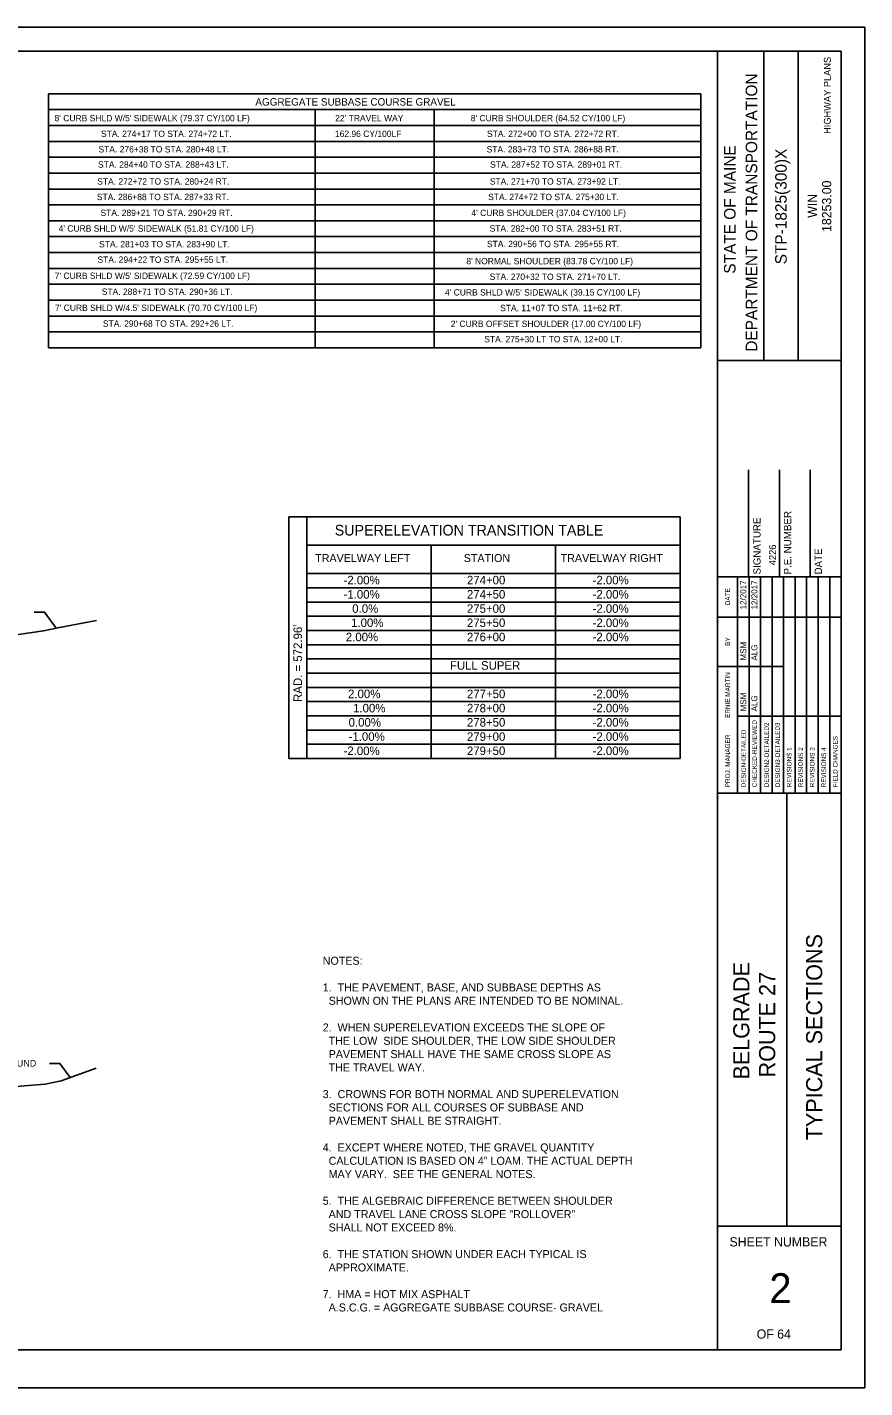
# Model space of a CAD drawing. Extents: x -60 to 130, y -2 to 86.
# Drawn here: x 75.3 to 129.5, y -2.4 to 85.6 of the extents above; entities that cross this region are included whole.
import ezdxf

# ---------------------------------------------------------------- set-up
doc = ezdxf.new("R2010")
doc.units = 0
for name, color, linetype in [('ANNOTATION', 7, 'Continuous'), ('BORDER', 7, 'Continuous'), ('PLOT BOUNDARY', 7, 'Continuous'), ('S_Roadway_Centerline', 7, 'Continuous')]:
    doc.layers.add(name, color=color, linetype=linetype)

msp = doc.modelspace()

# ---------------------------------------------------------------- linework, layer by layer
at = {"layer": 'ANNOTATION'}
for p, q in [((76.713, 81.246), (118.912, 81.246)), ((76.713, 81.246), (76.713, 64.821)), ((118.912, 81.246), (118.912, 64.821)), ((93.963, 80.22), (93.963, 64.821)), ((101.662, 80.22), (101.662, 64.821)), ((76.713, 79.193), (118.912, 79.193)), ((76.713, 78.166), (118.912, 78.166)), ((76.713, 76.113), (118.912, 76.113)), ((76.713, 76.113), (118.912, 76.113)), ((76.713, 75.087), (118.912, 75.087)), ((76.713, 73.034), (118.912, 73.034)), ((76.713, 72.007), (118.912, 72.007)), ((76.713, 70.98), (118.912, 70.98)), ((76.713, 68.927), (118.912, 68.927)), ((76.713, 66.874), (118.912, 66.874)), ((76.713, 65.847), (118.912, 65.847)), ((76.713, 64.821), (118.912, 64.821)), ((92.272, 53.891), (117.572, 53.891)), ((92.272, 53.891), (92.272, 38.251)), ((93.422, 53.891), (93.422, 38.251)), ((117.572, 53.891), (117.572, 38.251)), ((93.422, 52.051), (117.572, 52.051)), ((101.472, 52.051), (101.472, 38.251)), ((109.522, 52.051), (109.522, 38.251)), ((93.422, 50.211), (117.572, 50.211)), ((93.422, 50.211), (101.472, 50.211)), ((93.422, 49.291), (117.572, 49.291)), ((93.422, 48.371), (117.572, 48.371)), ((93.422, 47.451), (117.572, 47.451)), ((93.422, 46.531), (117.572, 46.531)), ((93.422, 45.611), (117.572, 45.611)), ((93.422, 44.691), (117.572, 44.691)), ((93.422, 43.771), (117.572, 43.771)), ((93.422, 42.851), (117.572, 42.851)), ((93.422, 41.931), (117.572, 41.931)), ((93.422, 41.011), (117.572, 41.011)), ((93.422, 40.091), (117.572, 40.091)), ((93.422, 39.171), (117.572, 39.171)), ((92.272, 38.251), (117.572, 38.251))]:
    msp.add_line(p, q, dxfattribs=at)
for points in [[(76.713, 80.22), (87.119, 80.22), (95.674, 80.22), (104.229, 80.22), (118.912, 80.22)], [(76.713, 77.14), (87.119, 77.14), (95.674, 77.14), (104.229, 77.14), (118.912, 77.14)], [(76.713, 74.06), (87.119, 74.06), (95.674, 74.06), (104.229, 74.06), (118.912, 74.06)], [(76.713, 69.954), (87.119, 69.954), (95.674, 69.954), (104.229, 69.954), (118.912, 69.954)], [(76.713, 67.901), (87.119, 67.901), (95.674, 67.901), (104.229, 67.901), (118.912, 67.901)], [(75.78, 47.721), (76.46, 47.721), (77.219, 46.681)], [(76.78, 18.537), (77.46, 18.537), (78.127, 17.622)]]:
    msp.add_lwpolyline(points, dxfattribs=at)
at = {"layer": 'BORDER'}
for p, q in [((128, 84), (0, 84)), ((120, 0.002), (120, 84.002)), ((122.983, 63.997), (122.983, 83.997)), ((125.219, 63.997), (125.219, 83.997)), ((128, 0.002), (128, 84.002)), ((120, 63.995), (128, 63.995)), ((122, 50.002), (122, 56.92)), ((124, 50.002), (124, 56.92)), ((126, 50.002), (126, 56.92)), ((120, 50.002), (128, 50.002)), ((120, 36.002), (128, 36.002)), ((124.473, 8.002), (124.473, 36.002)), ((120, 8.002), (128, 8.002)), ((0, 0), (128, 0))]:
    msp.add_line(p, q, dxfattribs=at)
for points in [[(121.292, 47.402), (121.292, 50.002)], [(121.292, 36.005), (121.292, 49.437)], [(122.038, 36.005), (122.038, 50.002)], [(122.783, 50.002), (122.783, 36.005)], [(123.528, 36.005), (123.528, 50.002)], [(124.274, 36.005), (124.274, 50.002)], [(125.019, 36.005), (125.019, 50.002)], [(125.764, 36.005), (125.764, 50.002)], [(126.51, 36.005), (126.51, 50.002)], [(127.255, 36.005), (127.255, 50.002)], [(120, 47.402), (128, 47.402)], [(120, 44.202), (121.292, 44.202)], [(121.292, 44.202), (124.273, 44.202)], [(121.292, 41.002), (128, 41.002)]]:
    msp.add_lwpolyline(points, dxfattribs=at)
at = {"layer": 'PLOT BOUNDARY'}
msp.add_lwpolyline([(-6.475, -2.447), (129.525, -2.447), (129.525, 85.553), (-6.475, 85.553)], close=True, dxfattribs=at)
at = {"layer": 'S_Roadway_Centerline'}
for points in [[(73.593, 46.137), (74.772, 46.277), (76.387, 46.507), (77.428, 46.724), (79.821, 47.173)], [(72.871, 16.659), (74.887, 17.051), (76.503, 17.192), (77.544, 17.409), (79.799, 18.233)]]:
    msp.add_lwpolyline(points, dxfattribs=at)

# ---------------------------------------------------------------- texts
at = {"layer": 'ANNOTATION'}
for s, height, p in [(' AGGREGATE SUBBASE COURSE GRAVEL', 0.47908, (89.923, 80.484)), ("8' CURB SHLD W/5' SIDEWALK (79.37 CY/100 LF)", 0.41064, (77.109, 79.468)), ("22' TRAVEL WAY", 0.41064, (95.267, 79.468)), ("8' CURB SHOULDER (64.52 CY/100 LF)", 0.41064, (104.035, 79.468)), ('STA. 274+17 TO STA. 274+72 LT.', 0.41064, (80.113, 78.455)), ('162.96 CY/100LF', 0.41064, (95.245, 78.455)), ('STA. 272+00 TO STA. 272+72 RT.', 0.41064, (105.086, 78.455)), ('STA. 276+38 TO STA. 280+48 LT.', 0.41064, (79.949, 77.452)), ('STA. 283+73 TO STA. 286+88 RT.', 0.41064, (105.06, 77.452)), ('STA. 284+40 TO STA. 288+43 LT.', 0.41064, (79.92, 76.467)), ('STA. 287+52 TO STA. 289+01 RT.', 0.41064, (105.284, 76.467)), ('STA. 272+72 TO STA. 280+24 RT.', 0.41064, (79.868, 75.373)), ('STA. 271+70 TO STA. 273+92 LT.', 0.41064, (105.265, 75.373)), ('STA. 286+88 TO STA. 287+33 RT.', 0.41064, (79.846, 74.369)), ('STA. 274+72 TO STA. 275+30 LT.', 0.41064, (105.155, 74.369)), ('STA. 289+21 TO STA. 290+29 RT.', 0.41064, (80.081, 73.343)), ("4' CURB SHOULDER (37.04 CY/100 LF)", 0.41064, (104.079, 73.343)), ("4' CURB SHLD W/5' SIDEWALK (51.81 CY/100 LF)", 0.41064, (77.373, 72.33)), ('STA. 282+00 TO STA. 283+51 RT.', 0.41064, (105.254, 72.331)), ('STA. 281+03 TO STA. 283+90 LT.', 0.41064, (79.989, 71.318)), ('STA. 290+56 TO STA. 295+55 RT.', 0.41064, (105.082, 71.327)), ('STA. 294+22 TO STA. 295+55 LT.', 0.41064, (79.883, 70.314)), ("8' NORMAL SHOULDER (83.78 CY/100 LF)", 0.41064, (103.747, 70.22)), ("7' CURB SHLD W/5' SIDEWALK (72.59 CY/100 LF)", 0.41064, (77.119, 69.273)), ('STA. 270+32 TO STA. 271+70 LT.', 0.41064, (105.258, 69.208)), ('STA. 288+71 TO STA. 290+36 LT.', 0.41064, (80.161, 68.24)), ("4' CURB SHLD W/5' SIDEWALK (39.15 CY/100 LF)", 0.41064, (102.364, 68.198)), ("7' CURB SHLD W/4.5' SIDEWALK (70.70 CY/100 LF)", 0.41064, (77.136, 67.201)), ('STA. 11+07 TO STA. 11+62 RT.', 0.41064, (105.932, 67.186)), ('STA. 290+68 TO STA. 292+26 LT.', 0.41064, (80.236, 66.177)), ("2' CURB OFFSET SHOULDER (17.00 CY/100 LF)", 0.41064, (102.742, 66.165)), ('STA. 275+30 LT TO STA. 12+00 LT.', 0.41064, (104.907, 65.172)), ('SUPERELEVATION TRANSITION TABLE', 0.69, (95.232, 52.676)), ('TRAVELWAY LEFT', 0.5175, (93.97, 50.961)), ('STATION', 0.5175, (103.58, 50.961)), ('TRAVELWAY RIGHT', 0.5175, (109.85, 50.961)), ('-2.00%', 0.552, (95.804, 49.516)), ('274+00', 0.552, (103.786, 49.516)), ('-2.00%', 0.552, (111.915, 49.516)), ('-1.00%', 0.552, (95.804, 48.596)), ('274+50', 0.552, (103.786, 48.596)), ('-2.00%', 0.552, (111.915, 48.596)), ('0.0%', 0.552, (96.367, 47.676)), ('275+00', 0.552, (103.786, 47.676)), ('-2.00%', 0.552, (111.915, 47.676)), ('1.00%', 0.552, (96.293, 46.756)), ('275+50', 0.552, (103.786, 46.756)), ('-2.00%', 0.552, (111.915, 46.756)), ('2.00%', 0.552, (95.952, 45.836)), ('276+00', 0.552, (103.786, 45.836)), ('-2.00%', 0.552, (111.915, 45.836)), ('FULL SUPER', 0.552, (102.687, 43.996)), ('2.00%', 0.552, (96.096, 42.156)), ('277+50', 0.552, (103.786, 42.156)), ('-2.00%', 0.552, (111.915, 42.156)), ('1.00%', 0.552, (96.422, 41.236)), ('278+00', 0.552, (103.786, 41.236)), ('-2.00%', 0.552, (111.915, 41.236)), ('0.00%', 0.552, (96.132, 40.316)), ('278+50', 0.552, (103.786, 40.316)), ('-2.00%', 0.552, (111.915, 40.316)), ('-1.00%', 0.552, (96.132, 39.396)), ('279+00', 0.552, (103.786, 39.396)), ('-2.00%', 0.552, (111.915, 39.396)), ('-2.00%', 0.552, (95.804, 38.476)), ('279+50', 0.552, (103.786, 38.476)), ('-2.00%', 0.552, (111.915, 38.476)), ('NOTES:', 0.5175, (94.456, 24.914)), ('1.  THE PAVEMENT, BASE, AND SUBBASE DEPTHS AS', 0.5175, (94.456, 23.189)), ('  SHOWN ON THE PLANS ARE INTENDED TO BE NOMINAL.', 0.5175, (94.456, 22.326)), ('2.  WHEN SUPERELEVATION EXCEEDS THE SLOPE OF', 0.5175, (94.456, 20.601)), ('  THE LOW  SIDE SHOULDER, THE LOW SIDE SHOULDER', 0.5175, (94.456, 19.739)), ('  PAVEMENT SHALL HAVE THE SAME CROSS SLOPE AS', 0.5175, (94.456, 18.876)), ('EXISTING GROUND', 0.4335, (70.482, 18.325)), ('  THE TRAVEL WAY.', 0.5175, (94.456, 18.014)), ('3.  CROWNS FOR BOTH NORMAL AND SUPERELEVATION', 0.5175, (94.456, 16.289)), ('  SECTIONS FOR ALL COURSES OF SUBBASE AND', 0.5175, (94.456, 15.426)), ('  PAVEMENT SHALL BE STRAIGHT.', 0.5175, (94.456, 14.564)), ('4.  EXCEPT WHERE NOTED, THE GRAVEL QUANTITY', 0.5175, (94.456, 12.839)), ('  CALCULATION IS BASED ON 4" LOAM. THE ACTUAL DEPTH', 0.5175, (94.456, 11.976)), ('  MAY VARY.  SEE THE GENERAL NOTES.', 0.5175, (94.456, 11.114)), ('5.  THE ALGEBRAIC DIFFERENCE BETWEEN SHOULDER', 0.5175, (94.456, 9.389)), ('  AND TRAVEL LANE CROSS SLOPE "ROLLOVER"', 0.5175, (94.456, 8.526)), ('  SHALL NOT EXCEED 8%.', 0.5175, (94.456, 7.664)), ('6.  THE STATION SHOWN UNDER EACH TYPICAL IS', 0.5175, (94.456, 5.939)), ('  APPROXIMATE.', 0.5175, (94.456, 5.076)), ('7.  HMA = HOT MIX ASPHALT', 0.5175, (94.456, 3.351)), ('  A.S.C.G. = AGGREGATE SUBBASE COURSE- GRAVEL', 0.5175, (94.456, 2.489))]:
    msp.add_text(s, height=height, dxfattribs=at).set_placement(p)
for s, height, p in [('4226', 0.45, (123.782, 50.753)), ("RAD. = 572.96'", 0.552, (93.118, 41.913))]:
    msp.add_text(s, height=height, rotation=90, dxfattribs=at).set_placement(p)
at = {"layer": 'BORDER'}
for s, height, p in [('HIGHWAY PLANS', 0.44721, (127.326, 78.652)), ('DEPARTMENT OF TRANSPORTATION', 0.7454, (122.565, 64.565)), ('STATE OF MAINE', 0.7454, (121.164, 69.609)), ('STP-1825(300)X', 0.7454, (124.473, 70.217)), ('18253.00', 0.5962, (127.356, 72.309)), ('WIN', 0.5962, (126.429, 73.224)), ('SIGNATURE', 0.4724, (122.784, 50.156)), ('P.E. NUMBER', 0.47244, (124.768, 50.156)), ('DATE', 0.4724, (126.753, 50.156)), ('12/2017', 0.3876, (121.858, 47.896)), ('12/2017', 0.3876, (122.574, 47.896)), ('DATE', 0.2971, (120.803, 48.167)), ('BY', 0.2971, (120.803, 45.55)), ('MSM', 0.3876, (121.858, 44.59)), ('ALG', 0.3876, (122.574, 44.59)), ('ERNIE MARTIN', 0.2982, (120.803, 40.878)), ('MSM', 0.3876, (121.858, 41.301)), ('ALG', 0.3876, (122.574, 41.301)), ('CHECKED-REVIEWED', 0.2982, (122.545, 36.393)), ('PROJ. MANAGER', 0.2982, (120.803, 36.393)), ('DESIGN-DETAILED', 0.2982, (121.829, 36.393)), ('DESIGN2-DETAILED2', 0.2982, (123.32, 36.393)), ('DESIGN3-DETAILED3', 0.2982, (124.035, 36.393)), ('REVISIONS 1', 0.2982, (124.781, 36.393)), ('REVISIONS 2', 0.2982, (125.526, 36.393)), ('REVISIONS 3', 0.2982, (126.271, 36.393)), ('REVISIONS 4', 0.2982, (127.017, 36.393)), ('FIELD CHANGES', 0.2982, (127.762, 36.393)), ('TYPICAL SECTIONS', 1.04342, (126.772, 13.562)), ('BELGRADE', 1.0434, (122.058, 17.487)), ('ROUTE 27', 1.0434, (123.727, 17.626))]:
    msp.add_text(s, height=height, rotation=90, dxfattribs=at).set_placement(p)
for s, height, p in [('SHEET NUMBER', 0.59622, (120.772, 6.693)), ('2', 1.936, (123.349, 3.026)), ('OF 64', 0.5962, (122.533, 0.73))]:
    msp.add_text(s, height=height, dxfattribs=at).set_placement(p)

doc.saveas('drawing.dxf')
